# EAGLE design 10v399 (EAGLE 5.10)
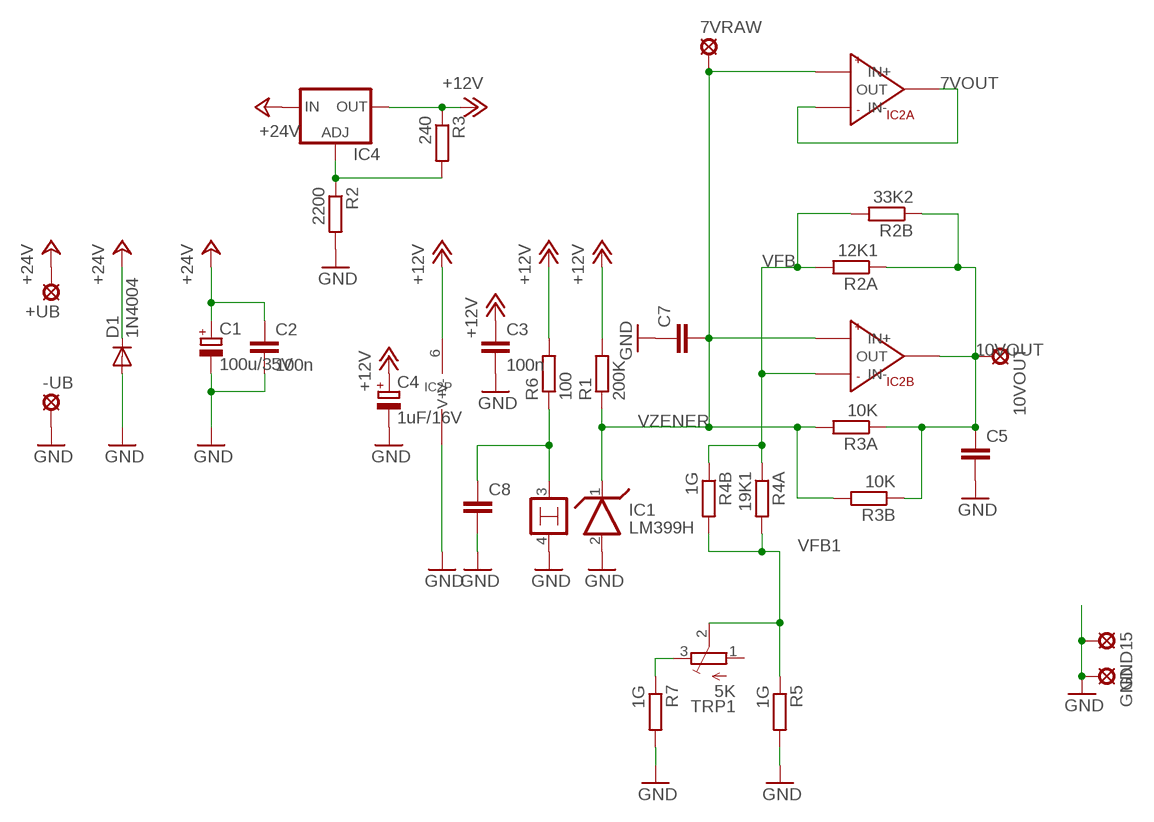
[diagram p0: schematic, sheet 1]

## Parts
7VRAW  LSP10  [LSP10]
10VOUT  LSP10  [LSP10]
+UB  LSP10  [LSP10]
-UB  LSP10  [LSP10]
C1  100u/35V  CPOL-EUE3.5-10  [E3,5-10]
C2  100n  C-EUC0805K  [C0805K]
C3  100n  C-EUC0805K  [C0805K]
C4  1uF/16V  CPOL-EUE2,5-6E  [E2,5-6E]
C5  C-EU025-024X044  [C025-024X044]
C7  C-EU025-024X044  [C025-024X044]
C8  C-EU025-024X044  [C025-024X044]
D1  1N4004  [DO41-10]
GND  LSP10  [LSP10]
GND15  LSP10  [LSP10]
IC1  LM399H  [TO39/4]
IC2  OP727  [SO8]
IC4  LM317TS  [317TS]
R1  200K  R-EU_0207/12  [0207/12]
R2  2200  R-EU_0207/12  [0207/12]
R2A  12K1  R-EU_0207/12  [0207/12]
R2B  33K2  R-EU_0207/12  [0207/12]
R3  240  R-EU_0207/12  [0207/12]
R3A  10K  R-EU_0207/12  [0207/12]
R3B  10K  R-EU_0207/12  [0207/12]
R4A  19K1  R-EU_0207/12  [0207/12]
R4B  1G  R-EU_0207/12  [0207/12]
R5  1G  R-EU_0207/12  [0207/12]
R6  100  R-EU_0207/12  [0207/12]
R7  1G  R-EU_0207/12  [0207/12]
TRP1  5K  TRIMPOTTC33X  [TC33X]

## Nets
7VOUT: IC2.7(A:OUT) IC2.8(A:IN-)
10VOUT: 10VOUT.MP C5.1 IC2.5(B:OUT) R2A.1 R2B.1 R3A.1 R3B.1
+12V: C3.1 C4.+ IC2.6(P:V+) IC4.2(OUT) R1.2 R3.1 R6.2
+24V: +UB.MP C1.+ C2.1 D1.C IC4.3(IN)
GND: -UB.MP C1.- C2.2 C3.2 C4.- C5.2 C7.1 C8.2 D1.A GND15.MP GND.MP IC1.2 IC1.4 IC2.2(P:V-) R2.2 R5.2 R7.2
N$1: C8.1 IC1.3 R6.1
N$2: IC4.1(ADJ) R2.1 R3.2
N$3: R7.1 TRP1.3(E)
VFB: IC2.4(B:IN-) R2A.2 R2B.2 R4A.1 R4B.1
VFB1: R4A.2 R4B.2 R5.1 TRP1.2(S)
VZENER: 7VRAW.MP C7.2 IC1.1 IC2.1(A:IN+) IC2.3(B:IN+) R1.1 R3A.2 R3B.2
Unconnected: TRP1.1(A)

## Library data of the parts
7VRAW 10VOUT +UB -UB GND GND15 = solpad:LSP10: SOLDER PAD
C1 C4 = rcl:CPOL-EU: POLARIZED CAPACITOR, European symbol
C2 C3 C5 C7 C8 = rcl:C-EU: CAPACITOR, European symbol
D1 = diode:1N4004: DIODE
IC1 = linear:LM399H: Precision Z DIODE
IC2 = 0000000-dg3hda:OP727
IC4 = v-reg:LM317TS: VOLTAGE REGULATOR
R1 R2 R2A R2B R3 R3A R3B R4A R4B R5-R7 = rcl:R-EU_: RESISTOR, European symbol
TRP1 = adafruit:TRIMPOT: SMT trimmer potentiometer part number TC33X http://www.ladyada.net/library/eagle

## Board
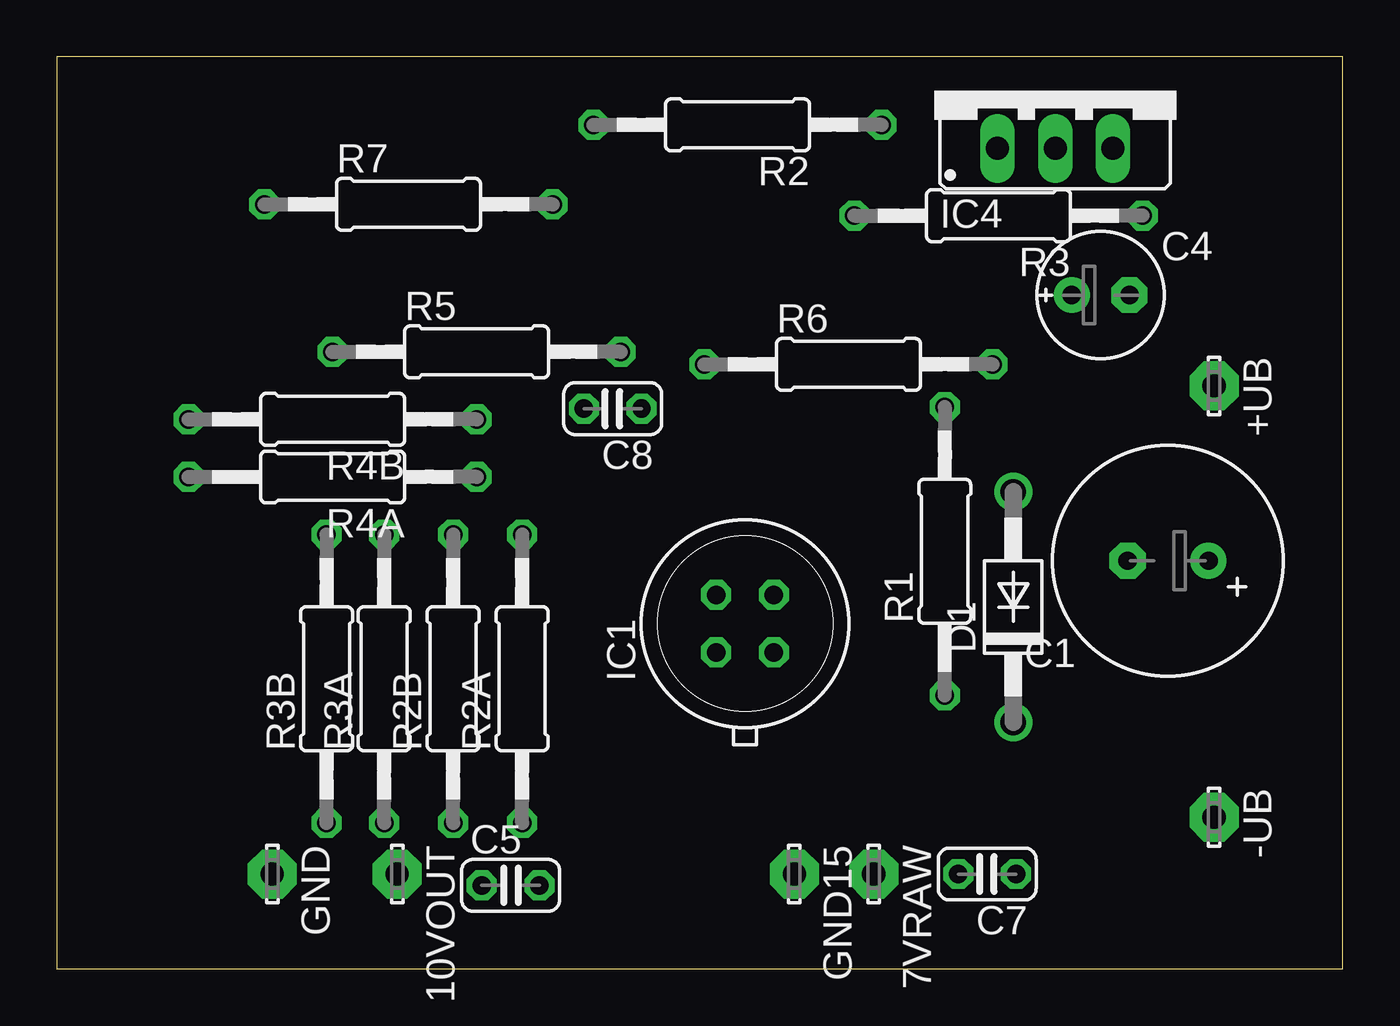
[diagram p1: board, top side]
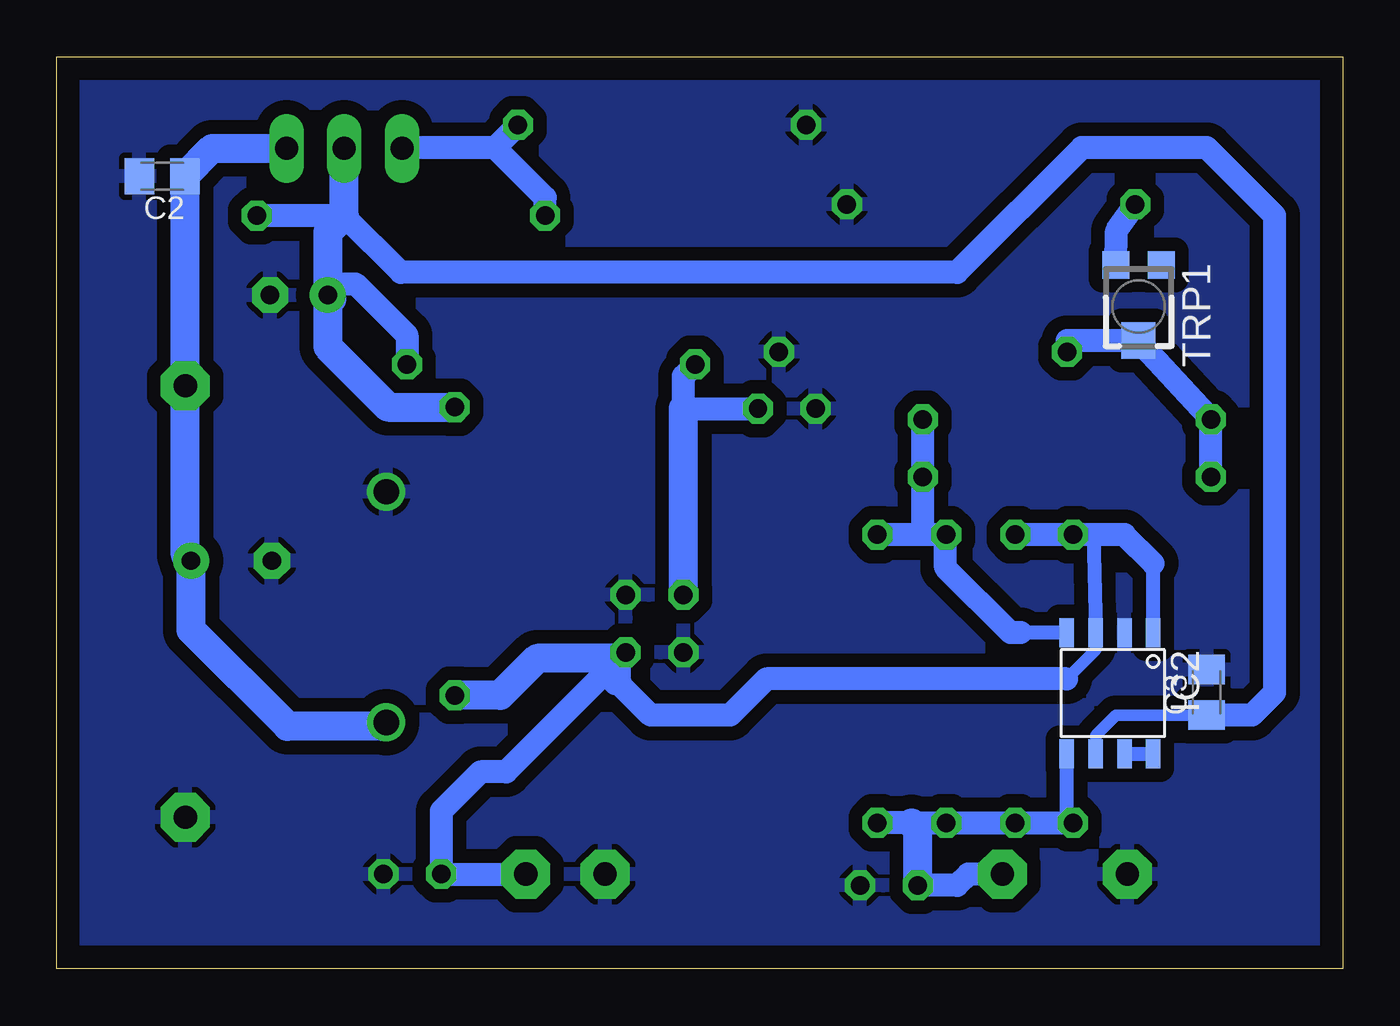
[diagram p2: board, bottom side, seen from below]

Size 56.67 x 40.18 mm. Coordinates in mm from the lower left corner, seen from the top.
Outline: 0,40.18 0,0 56.67,0 56.67,40.18 0,40.18
Copper layers (1*16): Top 0.035mm / dielectric 1.5mm / Bottom 0.035mm
Design rules "georg": minimum track width 20mil, minimum drill 24mil, track to track 24mil, track to pad 24mil, pad to pad 24mil, via to via 24mil, smd to smd 24mil, copper to edge 40mil, drill to drill 8mil, minimum pad ring 10mil, minimum via ring 8mil, stop-mask expansion 4mil, vias tented up to drill 0mil, thermal gap 10mil

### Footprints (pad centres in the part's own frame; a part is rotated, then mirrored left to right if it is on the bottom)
LSP10 = drill 1.016 pad 2.159 octagon: MP 0,0
E3,5-10 = drill 0.813 pad 1.6 round: + -1.778,0 | drill 0.813 pad 1.6 octagon: - 1.778,0
C0805K = smd 1.3 x 1.6: 1 -1,0; 2 1,0
E2,5-6E = drill 0.813 pad 1.575 round: + -1.27,0 | drill 0.813 pad 1.575 octagon: - 1.27,0
C025-024X044 = drill 0.813 octagon: 1 -1.27,0; 2 1.27,0
DO41-10 = drill 1.118 round: A 5.08,0; C -5.08,0
TO39/4 = drill 0.813 octagon: 1 -1.27,-1.27; 2 1.27,-1.27; 3 1.27,1.27; 4 -1.27,1.27
SO8 = smd 1.27 x 0.635: 1 -2.032,1.27; 2 -2.032,0; 3 -2.032,-1.27; 4 -2.032,-2.54; 5 3.302,-2.54; 6 3.302,-1.27; 7 3.302,0; 8 3.302,1.27
317TS = drill 1.016 long: 1 -2.54,-2.54; 2 0,-2.54; 3 2.54,-2.54
0207/12 = drill 0.813 octagon: 1 -6.35,0; 2 6.35,0
TC33X = smd 1.2 x 1.2: 1 -1,-1.825; 3 1,-1.825 | smd 1.5 x 1.6: 2 0,1.5

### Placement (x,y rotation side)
7VRAW  36,4.18 270 top
10VOUT  15,4.18 270 top
+UB  51,25.68 270 top
-UB  51,6.68 270 top
C1  48.97,17.98 180 top
C2  52.03,34.92 180 bottom
C3  6,12.18 90 bottom
C4  46,29.68 0 top
C5  20,3.68 0 top
C7  41,4.18 180 top
C8  24.5,24.68 180 top
D1  42.15,15.94 90 top
GND  9.5,4.18 270 top
GND15  32.5,4.18 270 top
IC1  30.33,15.21 90 top
IC2  9.62,12.78 270 bottom
IC4  44,38.68 0 top
R1  39.13,18.4 90 top
R2  30,37.18 180 top
R2A  20.51,12.78 90 top
R2B  17.47,12.78 90 top
R3  41.5,33.18 180 top
R3A  14.43,12.78 90 top
R3B  11.89,12.78 90 top
R4A  12.16,21.67 180 top
R4B  12.16,24.21 180 top
R5  18.5,27.18 0 top
R6  34.89,26.63 0 top
R7  15.5,33.68 0 top
TRP1  9,29.18 180 bottom

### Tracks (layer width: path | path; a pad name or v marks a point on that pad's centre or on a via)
7VOUT
  Bottom 0.61: IC2.7 IC2.8
10VOUT
  Bottom 0.61: IC2.5 12.16,6.43 R3B.1
  Bottom 1.016: R2A.1 19,6.43 R2B.1 R3A.1 R3B.1 | 10VOUT.MP 16.5,4.18 17,3.68 C5.1
  Bottom 1.27: C5.1 18.73,6.16 19,6.43
+12V
  Bottom 0.508: IC2.6 10.89,10.29 10,11.18 C3.1
  Bottom 1.016: C3.1 4,11.18 3,12.18 3,33.18 6,36.18 11.5,36.18 17,30.68 41.5,30.68 44,33.18 R3.1 | R6.2 41.24,27.92 43.5,30.18 44.73,30.18
  Bottom 1.27: C4.+ 44.73,30.18 44.73,32.45 44,33.18 IC4.2 | C4.+ 44.55,29.5 | R1.2 42.07,24.75 44.73,27.41 C4.+
+24V
  Bottom 1.27: D1.C 42.33,10.68 46.5,10.68 50.75,14.93 C1.+ 51,18.23 +UB.MP 51,34.89 C2.1 49.81,36.14 IC4.3
GND
  pour Bottom: 56,40.18 56,-0.02 0,-0.02 0,40.18
N$1
  Bottom 1.016: C8.1 29.06,24.68 29.06,26.11 R6.1
  Bottom 1.27: IC1.3 29.06,24.68
N$2
  Bottom 1.016: 37.35,36.18 41.27,36.18 | 37.35,36.18 R2.1 | R3.2 35.15,33.98 37.35,36.18
  Bottom 1.27: IC4.1 41.31,36.14 41.27,36.18
N$3
  Bottom 1.016: TRP1.3 9.97,32.51 R7.1
VFB
  Bottom 0.61: IC2.4 14.19,14.81
  Bottom 1.016: 18.5,19.13 R2B.2 17.5,19.1 17.5,17.68 14.63,14.81 14.19,14.81 | 18.5,19.13 R2A.2 | R4B.1 R4A.1 18.51,19.14 18.5,19.13
VFB1
  Bottom 1.016: R4A.2 R4B.2 6,24.4 TRP1.2 12.15,27.68 R5.1
VZENER
  Bottom 0.508: IC2.3 10.89,14.05 12.16,12.78
  Bottom 0.61: IC2.1 8.35,17.86 | R3B.2 11.89,19.18 11,19.18 IC2.3
  Bottom 1.016: 8.35,17.86 9.62,19.13 R3B.2 R3A.2 | 12.16,12.78 25.4,12.78 27,11.18 30.5,11.18 32,12.68 | IC1.1 36.86,8.68 38,8.68 39.73,6.95 C7.2 7VRAW.MP
  Bottom 1.27: R1.1 37.13,12.05 35.5,13.68 31.86,13.68 IC1.1 32,13.54 32,12.68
